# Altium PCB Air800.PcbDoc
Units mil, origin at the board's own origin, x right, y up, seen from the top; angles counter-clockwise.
Board outline 6000 x 4000 mil, 2 copper layers (Top, Bottom), stack 12.7 mil thick; 1 components, 0 nets, 54 pads, 0 vias.
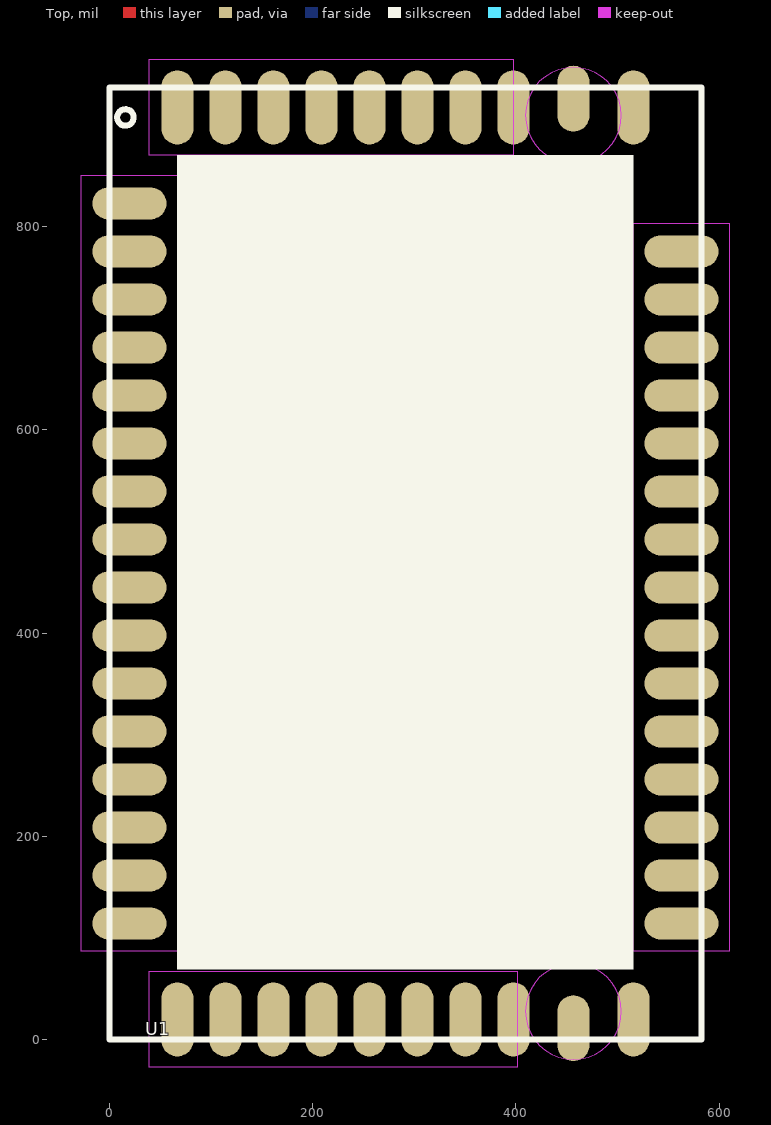
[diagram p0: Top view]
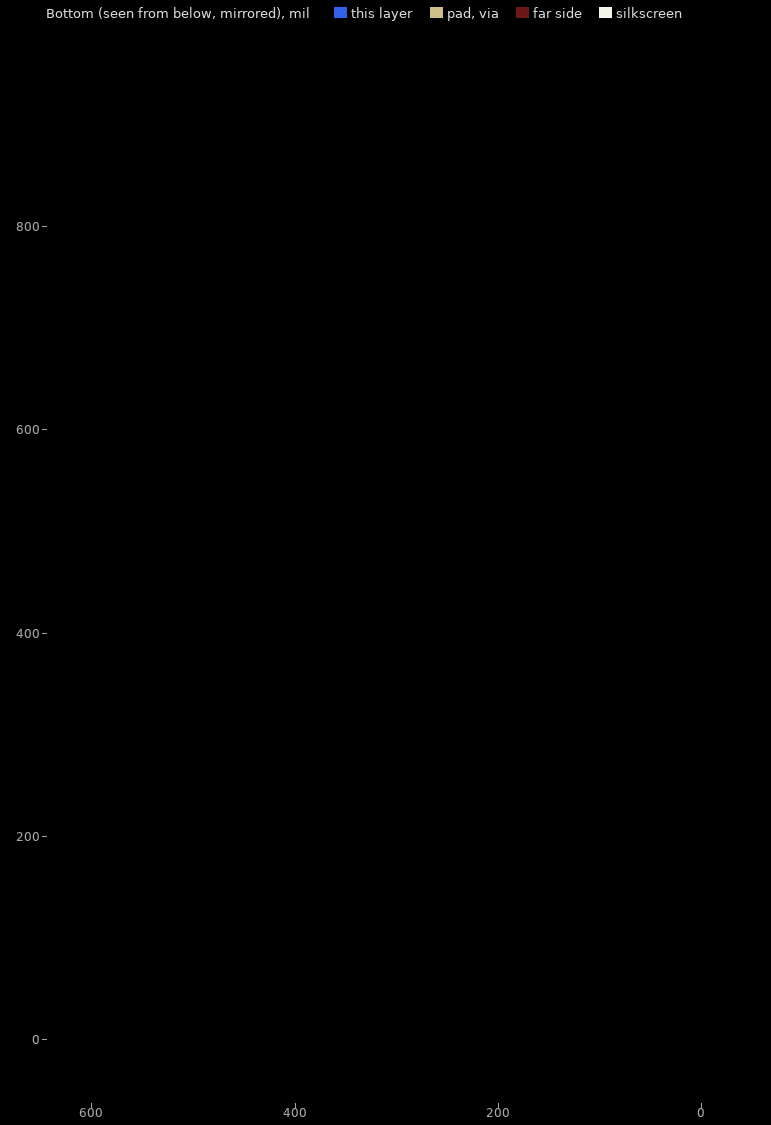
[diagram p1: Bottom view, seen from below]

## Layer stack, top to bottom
Solder Mask Top: solder mask 0.4, Solder Resist, Dk 3.5
Top: signal copper 1.35
Dielectric 1: dielectric 10, FR-4, Dk 4.3
Bottom: signal copper 1.35
Solder Mask Bottom: solder mask 0.4, Solder Resist, Dk 3.5

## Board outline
-8700,-8600.01 -2700,-8600.01 -2700,-4600.01 -8700,-4600.01

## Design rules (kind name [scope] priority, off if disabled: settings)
Clearance "Clearance - Default - DEFAULT- SMD" [IsVia vs IsSMTPin] p1: gap=6 ignorepadtopadclearanceinfootprint=FALSE
Clearance "Clearance - Default - DEFAULT - Via" [IsVia vs IsVia] p2: gap=6 ignorepadtopadclearanceinfootprint=FALSE
Clearance "Clearance - Default - DEFAULT - Net" [All] p3: gap=6 ignorepadtopadclearanceinfootprint=FALSE except(0: Arc-Hole Track-Hole SMDPad-Hole THPad-Hole Via-Hole Fill-Hole Poly-Hole Region-Hole Text-Hole; 10: Text-Text)
ComponentClearance "ComponentClearance - Default - DEFAULT" [All] p1: gap=6 collisioncheckmode=3 verticalgap=10 showdistances=FALSE
FanoutControl Fanout_Small [(CompPinCount < 5)] p3: bgadir=Out bgaviamode=Centered fanoutstyle=Auto fanoutdirection=OutThenIn viagrid=1 // Fanout_Small (Default Rule)
FanoutControl Fanout_SOIC [IsSOIC] p4: bgadir=Out bgaviamode=Centered fanoutstyle=Auto fanoutdirection=Alternating viagrid=1 // Fanout_SOIC (Default Rule)
HoleToHoleClearance "HoleToHoleClearance - Default - DEFAULT" [All] p1: gap=6 allowstackedmicrovias=TRUE
Length "Default Length" [All] p1: maxlimit=50000 minlimit=0
MaxMinImpedance "Default Impedance" [All] p1: minimum=50.00 maximum=150.0
ParallelSegment "Default Parallel Segment Adjasent" [All] p1: limit=1000 gap=200
ParallelSegment "Default Parallel Segment Same Layer" [All] p2: limit=1000 gap=200
PlaneConnect "Default PlaneConnect" [All] p1: planeconnectstyle=Relief reliefexpansion=20 reliefentries=0 reliefconductorwidth=15 reliefairgap=10
PolygonConnect "PolygonConnect - Default SMT" [IsSMTPin] p1: connectstyle=Relief reliefconductorwidth=10 reliefentries=4 polygonreliefangle="45 Angle" airgapwidth=10
PolygonConnect "PolygonConnect - Default Pad" [All] p2: connectstyle=Relief reliefconductorwidth=15 reliefentries=4 polygonreliefangle="45 Angle" airgapwidth=10
RoutingLayers "RoutingLayers - Default - DEFAULT" [All] p1: top layer_v5=TRUE bottom layer_v5=TRUE
RoutingPriority "RoutingPriority - Default - DEFAULT" [All] p1: routingpriority=3
RoutingTopology "Default Routing Topology" [All] p1: topology=Shortest
RoutingVias "RoutingVias - Default - DEFAULT" [All] p1: holewidth=37 width=55 viastyle="Through Hole" minholewidth=37 minwidth=55 maxholewidth=37 maxwidth=55
SMDToCorner "SMDToCorner - Default - DEFAULT" [All] p1: distance=60000
SolderMaskExpansion [All] p1: expansion=4
Width "Default Width" [All] p1: maxlimit=12 minlimit=12 preferedwidth=12
22 further rules are at their usual default settings.

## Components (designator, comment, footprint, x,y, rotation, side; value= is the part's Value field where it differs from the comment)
U1 "AIR800" AIR800 0,-0.01 r0 top

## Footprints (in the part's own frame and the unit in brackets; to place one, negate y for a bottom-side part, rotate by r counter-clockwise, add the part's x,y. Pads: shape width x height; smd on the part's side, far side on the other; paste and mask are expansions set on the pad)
AIR800 [mm]
  oval 1.85x0.8 smd: 1(0.5,20.9) 2(0.5,19.7) 3(0.5,18.5) 4(0.5,17.3) 5(0.5,16.1) 6(0.5,14.9) 7(0.5,13.7) 8(0.5,12.5) 9(0.5,11.3) 10(0.5,10.1) 11(0.5,8.9) 12(0.5,7.7) 13(0.5,6.5) 14(0.5,5.3) 15(0.5,4.1) 16(0.5,2.9) 27(14.3,2.9) 28(14.3,4.1) 29(14.3,5.3) 30(14.3,6.5) 31(14.3,7.7) 32(14.3,8.9) 33(14.3,10.1) 34(14.3,11.3) 35(14.3,12.5) 36(14.3,13.7) 37(14.3,14.9) 38(14.3,16.1) 39(14.3,17.3) 40(14.3,18.5) 41(14.3,19.7)
  oval 0.8x1.85 smd: 17(1.7,0.5) 18(2.9,0.5) 19(4.1,0.5) 20(5.3,0.5) 21(6.5,0.5) 22(7.7,0.5) 23(8.9,0.5) 24(10.1,0.5) 26(13.1,0.5) 42(13.1,23.3) 44(10.1,23.3) 45(8.9,23.3) 46(7.7,23.3) 47(6.5,23.3) 48(5.3,23.3) 49(4.1,23.3) 50(2.9,23.3) 51(1.7,23.3)
  oval 0.8x1.65 smd: 25(11.6,0.28) 43(11.6,23.52)
  rect 1.5x1.5 smd: 52(3.6,4.4) 53(7.4,11.9) 54(3.6,19.4)
  Top keep-out region: -0.7,21.6 1.7,21.6 1.7,2.2 -0.7,2.2 -0.7,21.6
  Top keep-out region: 1,1.7 10.2,1.7 10.2,-0.7 1,-0.7 1,1.7
  Top keep-out region: 13.1,20.4 15.5,20.4 15.5,2.2 13.1,2.2 13.1,20.4
  Top keep-out region: 1,24.5 10.1,24.5 10.1,22.1 1,22.1 1,24.5
  Top keep-out region: 12.8,23.1 12.709,23.559 12.449,23.949 12.059,24.209 11.6,24.3 11.6,24.3 11.141,24.209 10.751,23.949 10.491,23.559 10.4,23.1 10.4,23.1 10.491,22.641 10.751,22.251 11.141,21.991 11.6,21.9 11.6,21.9 12.059,21.991 12.449,22.251 12.709,22.641 12.8,23.1
  Top keep-out region: 12.8,0.7 12.709,1.159 12.449,1.549 12.059,1.809 11.6,1.9 11.6,1.9 11.141,1.809 10.751,1.549 10.491,1.159 10.4,0.7 10.4,0.7 10.491,0.241 10.751,-0.149 11.141,-0.409 11.6,-0.5 11.6,-0.5 12.059,-0.409 12.449,-0.149 12.709,0.241 12.8,0.7
  silkscreen extent 0,0 14.8,23.8

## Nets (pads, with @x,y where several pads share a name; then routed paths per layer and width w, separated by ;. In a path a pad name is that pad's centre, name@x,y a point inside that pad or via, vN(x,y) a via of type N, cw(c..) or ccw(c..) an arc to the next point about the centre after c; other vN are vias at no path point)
pads on no net: U1.1 U1.2 U1.3 U1.4 U1.5 U1.6 U1.7 U1.8 U1.9 U1.10 U1.11 U1.12 U1.13 U1.14 U1.15 U1.16 U1.17 U1.18 U1.19 U1.20 U1.21 U1.22 U1.23 U1.24 U1.25 U1.26 U1.27 U1.28 U1.29 U1.30 U1.31 U1.32 U1.33 U1.34 U1.35 U1.36 U1.37 U1.38 U1.39 U1.40 U1.41 U1.42 U1.43 U1.44 U1.45 U1.46 U1.47 U1.48 U1.49 U1.50 U1.51 U1.52 U1.53 U1.54

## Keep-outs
Top:
  region: 94.23,255.73 212.66,255.73 212.66,216.55 94.23,216.55 94.23,255.73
